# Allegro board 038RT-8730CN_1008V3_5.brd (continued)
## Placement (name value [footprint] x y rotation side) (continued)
NOREF#1801  -  []  182.03 253.76 90 top
NOREF#1802  -  []  328.29 191.82 0 top
NOREF#1803  -  []  242.32 277.38 0 top
NOREF#1804  -  []  227.55 359.7 0 top
NOREF#1805  -  []  388.3 185 90 top
NOREF#1806  -  []  428.82 224.67 0 top
NOREF#1807  -  []  232.52 183.21 90 top
NOREF#1808  -  []  508.3 275.9 90 top
NOREF#1809  -  []  333.23 206.23 0 top
NOREF#1810  -  []  410.97 245.28 0 top
NOREF#1811  -  []  324.25 177.55 0 top
NOREF#1812  -  []  406.87 194.07 0 top
NOREF#1813  -  []  407.38 198.01 0 top
NOREF#1814  -  []  364.8 184.64 0 top
NOREF#1815  -  []  311.08 208.98 0 top
NOREF#1816  -  []  389.18 198.29 90 top
NOREF#1817  -  []  410.3 206.6 90 top
NOREF#1818  -  []  320.97 84.76 0 top
NOREF#1819  -  []  333.28 209.37 90 top
NOREF#1820  -  []  333.32 257.97 0 top
NOREF#1821  -  []  196.58 203 90 top
NOREF#1822  -  []  279.69 296.22 0 top
NOREF#1823  -  []  406.9 260.19 0 top
NOREF#1824  -  []  297.43 210.27 90 top
NOREF#1825  -  []  520.17 246.5 90 top
NOREF#1826  -  []  502.07 202.24 90 top
NOREF#1827  -  []  404.75 228.96 90 top
NOREF#1828  -  []  275.93 207.58 90 top
NOREF#1829  -  []  429.34 243.1 0 top
NOREF#1830  -  []  281.8 294.95 0 top
NOREF#1831  -  []  320.37 202.42 0 top
NOREF#1832  -  []  323.07 86.06 0 top
NOREF#1833  -  []  403.93 127.85 90 top
NOREF#1834  -  []  393.3 230 0 top
NOREF#1835  -  []  325.7 184.32 90 top
NOREF#1836  -  []  373.23 262.51 0 top
NOREF#1837  -  []  269.18 260.49 90 top
NOREF#1838  -  []  296.84 171.61 0 top
NOREF#1839  -  []  408.95 196.35 0 top
NOREF#1840  -  []  204.8 424.5 90 top
NOREF#1841  -  []  521.42 202.06 0 top
NOREF#1842  -  []  477.82 173.08 0 top
NOREF#1843  -  []  294.58 298.52 90 top
NOREF#1844  -  []  413.23 206.23 0 top
NOREF#1845  -  []  305.3 188 90 top
NOREF#1846  -  []  209.66 201.6 90 top
NOREF#1847  -  []  452.91 239.5 0 top
NOREF#1848  -  []  412.33 204.49 0 top
NOREF#1849  -  []  375.13 272.93 90 top
NOREF#1850  -  []  182.03 282.65 90 top
NOREF#1851  -  []  306.68 169.03 0 top
NOREF#1852  -  []  354.08 200.75 90 top
NOREF#1853  -  []  269.18 258.29 90 top
NOREF#1854  -  []  362.9 209.33 0 top
NOREF#1855  -  []  187.33 183.21 0 top
NOREF#1856  -  []  284.75 288.95 90 top
NOREF#1857  -  []  146.75 421.44 0 top
NOREF#1858  -  []  477.74 261.14 0 top
NOREF#1859  -  []  290.99 252.65 0 top
NOREF#1860  -  []  367.56 210 0 top
NOREF#1861  -  []  328.5 270.01 0 top
NOREF#1862  -  []  336.14 200.99 0 top
NOREF#1863  -  []  230.64 271.58 0 top
NOREF#1864  -  []  364.53 264.54 90 top
NOREF#1865  -  []  329.7 176.75 0 top
NOREF#1866  -  []  329.66 195.8 90 top
NOREF#1867  -  []  482.51 99.06 0 top
NOREF#1868  -  []  548.8 23.5 90 top
NOREF#1869  -  []  52.77 6.56 0 top
NOREF#1870  -  []  335.42 199.88 90 top
NOREF#1871  -  []  238.16 228.9 90 top
NOREF#1872  -  []  247.68 245.33 0 top
NOREF#1873  -  []  254.87 194.3 90 top
NOREF#1874  -  []  454.88 278.39 0 top
NOREF#1875  -  []  409.3 191.52 90 top
NOREF#1876  -  []  366.25 195.33 0 top
NOREF#1877  -  []  239.54 299.08 0 top
NOREF#1878  -  []  284.8 188.34 0 top
NOREF#1879  -  []  268.3 225 0 top
NOREF#1880  -  []  363.34 213.34 0 top
NOREF#1881  -  []  327.65 84.79 90 top
NOREF#1882  -  []  443.36 102.82 0 top
NOREF#1883  -  []  428.36 281.49 0 top
NOREF#1884  -  []  403.63 206.35 0 top
NOREF#1885  -  []  442.87 257.56 0 top
NOREF#1886  -  []  376.84 171.61 0 top
NOREF#1887  -  []  497.31 212.21 90 top
NOREF#1888  -  []  409.87 196.73 0 top
NOREF#1889  -  []  374.43 263.38 90 top
NOREF#1890  -  []  370.67 250.47 90 top
NOREF#1891  -  []  253.73 219.45 0 top
NOREF#1892  -  []  349.34 243.1 0 top
NOREF#1893  -  []  386.14 179.9 90 top
NOREF#1894  -  []  410.07 245.6 0 top
NOREF#1895  -  []  450.32 102.82 0 top
NOREF#1896  -  []  233.84 210.26 90 top
NOREF#1897  -  []  511.9 279.95 90 top
NOREF#1898  -  []  227.67 287.48 0 top
NOREF#1899  -  []  288.3 205 0 top
NOREF#1900  -  []  333.29 151.39 0 top
NOREF#1901  -  []  408.3 205 90 top
NOREF#1902  -  []  308.3 245 90 top
NOREF#1903  -  []  272.8 23.5 90 top
NOREF#1904  -  []  328.53 227.49 0 top
NOREF#1905  -  []  321.7 269.33 0 top
NOREF#1906  -  []  219.44 253.19 90 top
NOREF#1907  -  []  179.95 227.88 90 top
NOREF#1908  -  []  216.24 271.58 0 top
NOREF#1909  -  []  208.01 295.88 90 top
NOREF#1910  -  []  493.99 285.39 0 top
NOREF#1911  -  []  368.54 251.43 0 top
NOREF#1912  -  []  514.57 195.59 90 top
NOREF#1913  -  []  520.17 255.14 90 top
NOREF#1914  -  []  428.82 265.97 0 top
NOREF#1915  -  []  329.7 209.37 90 top
NOREF#1916  -  []  249.33 239.72 0 top
NOREF#1917  -  []  52.77 405.06 0 top
NOREF#1918  -  []  328.89 191.43 0 top
NOREF#1919  -  []  453.25 245.41 90 top
NOREF#1920  -  []  505.42 294.03 0 top
NOREF#1921  -  []  321.57 201.78 90 top
NOREF#1922  -  []  453.76 170.92 0 top
NOREF#1923  -  []  410.97 192.03 90 top
NOREF#1924  -  []  326.35 187.8 0 top
NOREF#1925  -  []  285.3 262 0 top
NOREF#1926  -  []  414.11 86.06 0 top
NOREF#1927  -  []  400.89 251.48 90 top
NOREF#1928  -  []  288.3 265 0 top
NOREF#1929  -  []  186.51 258.1 0 top
NOREF#1930  -  []  477.74 192.56 0 top
NOREF#1931  -  []  227.67 184.61 0 top
NOREF#1932  -  []  259.35 302.27 0 top
NOREF#1933  -  []  288.24 300.71 90 top
NOREF#1934  -  []  391.54 183.1 0 top
NOREF#1935  -  []  407.82 269.36 90 top
NOREF#1936  -  []  284.53 263.69 90 top
NOREF#1937  -  []  413.32 260.2 0 top
NOREF#1938  -  []  31.09 337.83 90 top
NOREF#1939  -  []  325.98 187.8 0 top
NOREF#1940  -  []  219.44 271.58 90 top
NOREF#1941  -  []  265.98 263.69 0 top
NOREF#1942  -  []  403.33 264.33 0 top
NOREF#1943  -  []  213.05 131.66 0 top
NOREF#1944  -  []  272.38 290.7 90 top
NOREF#1945  -  []  414.5 189.29 90 top
NOREF#1946  -  []  323.43 93.57 90 top
NOREF#1947  -  []  409.93 179.45 0 top
NOREF#1948  -  []  508.3 207.32 90 top
NOREF#1949  -  []  343.63 396.4 0 top
NOREF#1950  -  []  459.82 218.67 90 top
NOREF#1951  -  []  373.32 257.97 0 top
NOREF#1952  -  []  191.18 271.58 0 top
NOREF#1953  -  []  193.38 278.84 0 top
NOREF#1954  -  []  430.14 189.48 0 top
NOREF#1955  -  []  323.34 273.34 0 top
NOREF#1956  -  []  400.37 260.97 0 top
NOREF#1957  -  []  349.3 283 0 top
NOREF#1958  -  []  328.82 209.11 90 top
NOREF#1959  -  []  284.1 259 0 top
NOREF#1960  -  []  155.68 253.76 0 top
NOREF#1961  -  []  367.08 197.69 0 top
NOREF#1962  -  []  50.8 465 0 top
NOREF#1963  -  []  182.03 236.93 0 top
NOREF#1964  -  []  326.51 167.49 90 top
NOREF#1965  -  []  401.57 262.44 90 top
NOREF#1966  -  []  182.03 202.64 90 top
NOREF#1967  -  []  13.59 370.31 90 top
NOREF#1968  -  []  413.47 192.26 0 top
NOREF#1969  -  []  366.33 255.34 90 top
NOREF#1970  -  []  208.01 253.19 90 top
NOREF#1971  -  []  217.72 377.26 90 top
NOREF#1972  -  []  269.3 223 0 top
NOREF#1973  -  []  181.48 224.7 90 top
NOREF#1974  -  []  369.3 251.52 90 top
NOREF#1975  -  []  193.33 292.92 0 top
NOREF#1976  -  []  373.02 196.8 0 top
NOREF#1977  -  []  454.88 286.79 0 top
NOREF#1978  -  []  372.19 252 90 top
NOREF#1979  -  []  211.84 261.59 0 top
NOREF#1980  -  []  293.34 191.84 0 top
NOREF#1981  -  []  412 84.76 0 top
NOREF#1982  -  []  514.57 191.19 90 top
NOREF#1983  -  []  508.74 296.69 90 top
NOREF#1984  -  []  408.3 205 0 top
NOREF#1985  -  []  128.63 387.18 0 top
NOREF#1986  -  []  175.18 199.36 0 top
NOREF#1987  -  []  458.33 169.65 90 top
NOREF#1988  -  []  310.61 379.8 0 top
NOREF#1989  -  []  505.67 245.66 90 top
NOREF#1990  -  []  288.51 196.36 0 top
NOREF#1991  -  []  331.52 194.76 90 top
NOREF#1992  -  []  459.65 361.76 90 top
NOREF#1993  -  []  395.48 194.44 90 top
NOREF#1994  -  []  286.08 200.19 0 top
NOREF#1995  -  []  374.73 175.45 0 top
NOREF#1996  -  []  459.82 259.97 90 top
NOREF#1997  -  []  439.67 178.77 90 top
NOREF#1998  -  []  272.28 201.89 0 top
NOREF#1999  -  []  488.59 232.71 0 top
NOREF#2000  -  []  30.51 353.75 90 top
NOREF#2001  -  []  406.55 171.34 90 top
NOREF#2002  -  []  368.89 251.43 0 top
NOREF#2003  -  []  494.38 382.36 0 top
NOREF#2004  -  []  256.93 274.01 90 top
NOREF#2005  -  []  369.82 186.49 0 top
NOREF#2006  -  []  329.67 209.11 90 top
NOREF#2007  -  []  221.62 183.21 0 top
NOREF#2008  -  []  433.17 322.65 90 top
NOREF#2009  -  []  442.87 195.99 0 top
NOREF#2010  -  []  317.13 95.22 90 top
NOREF#2011  -  []  517.92 250.53 0 top
NOREF#2012  -  []  233.84 271.58 90 top
NOREF#2013  -  []  366.29 238.5 90 top
NOREF#2014  -  []  405.7 196.69 0 top
NOREF#2015  -  []  286.9 200.19 0 top
NOREF#2016  -  []  189.51 190.05 90 top
NOREF#2017  -  []  393.33 201.92 0 top
NOREF#2018  -  []  453.25 211.76 0 top
NOREF#2019  -  []  260.08 161.59 90 top
NOREF#2020  -  []  386.14 239.9 90 top
NOREF#2021  -  []  414.57 280.31 90 top
NOREF#2022  -  []  363.33 266.03 0 top
NOREF#2023  -  []  466.06 360.96 90 top
NOREF#2024  -  []  230.64 237.29 0 top
NOREF#2025  -  []  46.32 412.09 90 top
NOREF#2026  -  []  323.33 206.03 0 top
NOREF#2027  -  []  326.9 260.19 0 top
NOREF#2028  -  []  196.58 175.97 90 top
NOREF#2029  -  []  327.65 82.22 90 top
NOREF#2030  -  []  291.52 194.76 90 top
NOREF#2031  -  []  300.3 273 0 top
NOREF#2032  -  []  342.54 75.65 0 top
NOREF#2033  -  []  389.3 283 0 top
NOREF#2034  -  []  291.55 189.53 90 top
NOREF#2035  -  []  285.7 246.14 90 top
NOREF#2036  -  []  257.93 230.02 0 top
NOREF#2037  -  []  373.3 257.5 90 top
NOREF#2038  -  []  383.61 136.74 0 top
NOREF#2039  -  []  465.73 282.2 90 top
NOREF#2040  -  []  365.3 202 0 top
NOREF#2041  -  []  285.68 245.52 90 top
NOREF#2042  -  []  406.57 194.43 90 top
NOREF#2043  -  []  285.98 187.8 0 top
NOREF#2044  -  []  491.79 276.99 0 top
NOREF#2045  -  []  511.37 267.36 0 top
NOREF#2046  -  []  202.61 278.84 0 top
NOREF#2047  -  []  454.88 183.92 0 top
NOREF#2048  -  []  330.8 293.85 0 top
NOREF#2049  -  []  285.7 196.05 0 top
NOREF#2050  -  []  400.8 260 0 top
NOREF#2051  -  []  313.3 240 90 top
NOREF#2052  -  []  453.76 205.21 0 top
NOREF#2053  -  []  471.77 359.7 0 top
NOREF#2054  -  []  417.78 228.89 90 top
NOREF#2055  -  []  505.92 291.03 0 top
NOREF#2056  -  []  514.57 264.17 90 top
NOREF#2057  -  []  366.38 296.27 90 top
NOREF#2058  -  []  308.3 185 90 top
NOREF#2059  -  []  211.05 377.23 0 top
NOREF#2060  -  []  366.3 254.08 90 top
NOREF#2061  -  []  500.02 290.83 90 top
NOREF#2062  -  []  457.37 375.96 0 top
NOREF#2063  -  []  242.32 243.09 0 top
NOREF#2064  -  []  329.61 259.55 90 top
NOREF#2065  -  []  333.02 196.8 0 top
NOREF#2066  -  []  414.58 288.89 0 top
NOREF#2067  -  []  373.03 213.89 0 top
NOREF#2068  -  []  382.62 166.16 90 top
NOREF#2069  -  []  164.15 -41.86 90 top
NOREF#2070  -  []  406.99 187.3 90 top
NOREF#2071  -  []  262.63 166.67 90 top
NOREF#2072  -  []  508.74 246.5 90 top
NOREF#2073  -  []  210.19 208.86 0 top
NOREF#2074  -  []  319.09 132.51 90 top
NOREF#2075  -  []  182.03 248.36 0 top
NOREF#2076  -  []  52.77 6.56 0 top
NOREF#2077  -  []  326.58 200.49 90 top
NOREF#2078  -  []  372.9 173.55 90 top
NOREF#2079  -  []  333.23 207.72 0 top
NOREF#2080  -  []  377.34 263.1 90 top
NOREF#2081  -  []  288.51 256.36 0 top
NOREF#2082  -  []  300.83 71.55 0 top
NOREF#2083  -  []  414.22 259.67 0 top
NOREF#2084  -  []  286.58 247.88 0 top
NOREF#2085  -  []  360.37 259.6 0 top
NOREF#2086  -  []  269.18 256.09 90 top
NOREF#2087  -  []  365.97 193.75 0 top
NOREF#2088  -  []  412.9 169.15 90 top
NOREF#2089  -  []  276.16 202.17 90 top
NOREF#2090  -  []  280.8 260 0 top
NOREF#2091  -  []  373.28 209.37 90 top
NOREF#2092  -  []  351.72 126.78 90 top
NOREF#2093  -  []  318.05 118.31 90 top
NOREF#2094  -  []  431.54 243.1 0 top
NOREF#2095  -  []  230.64 175.97 0 top
NOREF#2096  -  []  411.82 205.24 0 top
NOREF#2097  -  []  468.16 259.74 0 top
NOREF#2098  -  []  226.24 203 0 top
NOREF#2099  -  []  381.07 123.59 0 top
NOREF#2100  -  []  283.98 198.4 90 top
NOREF#2101  -  []  354.28 268.98 90 top
NOREF#2102  -  []  293.33 260.2 0 top
NOREF#2103  -  []  335.29 184.5 0 top
NOREF#2104  -  []  334.73 172.88 0 top
NOREF#2105  -  []  366.94 209.1 90 top
NOREF#2106  -  []  343.25 169.03 0 top
NOREF#2107  -  []  276.89 198.83 90 top
NOREF#2108  -  []  319.69 296.22 0 top
NOREF#2109  -  []  242.32 208.8 0 top
NOREF#2110  -  []  414.73 172.88 0 top
NOREF#2111  -  []  379.43 227.49 90 top
NOREF#2112  -  []  488.59 290.83 90 top
NOREF#2113  -  []  192.73 258.1 0 top
NOREF#2114  -  []  191.18 168.71 0 top
NOREF#2115  -  []  179.95 250.74 90 top
NOREF#2116  -  []  366.33 247.99 90 top
NOREF#2117  -  []  336.44 260.67 0 top
NOREF#2118  -  []  406.4 287.55 90 top
NOREF#2119  -  []  468.16 225.45 0 top
NOREF#2120  -  []  477.74 268.4 0 top
NOREF#2121  -  []  284.8 196.37 0 top
NOREF#2122  -  []  276.79 294.51 0 top
NOREF#2123  -  []  337.34 263.1 90 top
NOREF#2124  -  []  208.01 203 90 top
NOREF#2125  -  []  219.44 237.29 90 top
NOREF#2126  -  []  285.68 255.34 90 top
NOREF#2127  -  []  361.57 199.65 90 top
NOREF#2128  -  []  228.44 210.26 0 top
NOREF#2129  -  []  400.37 200.29 0 top
NOREF#2130  -  []  484.5 170.54 90 top
NOREF#2131  -  []  309.3 223 0 top
NOREF#2132  -  []  285.7 267.17 0 top
NOREF#2133  -  []  412.33 265.91 0 top
NOREF#2134  -  []  292.33 267.4 0 top
NOREF#2135  -  []  374.67 191.62 90 top
NOREF#2136  -  []  459.82 252.96 90 top
NOREF#2137  -  []  280.37 259.6 0 top
NOREF#2138  -  []  477.16 273.79 90 top
NOREF#2139  -  []  498.22 360.96 90 top
NOREF#2140  -  []  259.78 233.58 0 top
NOREF#2141  -  []  271.3 222 0 top
NOREF#2142  -  []  182.03 225.5 0 top
NOREF#2143  -  []  233.84 237.29 90 top
NOREF#2144  -  []  229.02 85.95 0 top
NOREF#2145  -  []  369.67 209.11 90 top
NOREF#2146  -  []  295.29 244.5 0 top
NOREF#2147  -  []  301.44 169.36 0 top
NOREF#2148  -  []  210.19 286.08 0 top
NOREF#2149  -  []  286.3 193.44 90 top
NOREF#2150  -  []  240.95 258.24 0 top
NOREF#2151  -  []  317.15 228.96 0 top
NOREF#2152  -  []  369.77 252.68 0 top
NOREF#2153  -  []  329.29 195.34 90 top
NOREF#2154  -  []  196.33 223.81 90 top
NOREF#2155  -  []  446.07 165.85 90 top
NOREF#2156  -  []  283.66 273.64 90 top
NOREF#2157  -  []  221.09 201.6 90 top
NOREF#2158  -  []  366.96 142.02 90 top
NOREF#2159  -  []  477.16 208.41 0 top
NOREF#2160  -  []  290.67 251.75 90 top
NOREF#2161  -  []  437.91 103.62 0 top
NOREF#2162  -  []  521.42 190.63 0 top
NOREF#2163  -  []  365.68 195.34 90 top
NOREF#2164  -  []  485.88 169.52 90 top
NOREF#2165  -  []  179.95 170.73 90 top
NOREF#2166  -  []  284.8 186.46 0 top
NOREF#2167  -  []  454.88 218.21 0 top
NOREF#2168  -  []  282.9 209.32 0 top
NOREF#2169  -  []  405.92 226.51 0 top
NOREF#2170  -  []  417.34 204.47 90 top
NOREF#2171  -  []  502.07 167.95 90 top
NOREF#2172  -  []  369.11 251.32 90 top
NOREF#2173  -  []  500.02 232.71 0 top
NOREF#2174  -  []  429.36 166.16 90 top
NOREF#2175  -  []  52.77 6.56 0 top
NOREF#2176  -  []  329.13 251.83 90 top
NOREF#2177  -  []  325.68 255.34 90 top
NOREF#2178  -  []  309.3 283 0 top
NOREF#2179  -  []  508.74 212.21 90 top
NOREF#2180  -  []  405.98 187.8 0 top
NOREF#2181  -  []  337.34 264.47 90 top
NOREF#2182  -  []  321.8 294.95 0 top
NOREF#2183  -  []  323.63 264.65 0 top
NOREF#2184  -  []  414.57 222.51 90 top
NOREF#2185  -  []  404.8 186.46 90 top
NOREF#2186  -  []  453.02 216.31 90 top
NOREF#2187  -  []  333.28 269.37 90 top
NOREF#2188  -  []  366.86 77.94 0 top
NOREF#2189  -  []  405.7 186.14 90 top
NOREF#2190  -  []  191.18 203 0 top
NOREF#2191  -  []  407.56 270 0 top
NOREF#2192  -  []  349.3 186 90 top
NOREF#2193  -  []  368.09 255.99 0 top
NOREF#2194  -  []  237.43 231.77 0 top
NOREF#2195  -  []  297.34 260.35 90 top
NOREF#2196  -  []  244.11 194.94 90 top
NOREF#2197  -  []  294.57 218.11 90 top
NOREF#2198  -  []  372.7 250.29 0 top
NOREF#2199  -  []  377.34 264.47 90 top
NOREF#2200  -  []  362.9 269.33 0 top
NOREF#2201  -  []  296.44 204.79 0 top
NOREF#2202  -  []  336.84 171.61 0 top
NOREF#2203  -  []  351.54 183.1 0 top
NOREF#2204  -  []  326.57 194.43 90 top
NOREF#2205  -  []  294.3 260.8 90 top
NOREF#2206  -  []  395.24 294.13 0 top
NOREF#2207  -  []  414.12 300.11 0 top
NOREF#2208  -  []  267.91 225.75 90 top
NOREF#2209  -  []  553.44 322.27 90 top
NOREF#2210  -  []  50.8 465 0 top
NOREF#2211  -  []  413.93 213.57 0 top
NOREF#2212  -  []  452.5 88.62 0 top
NOREF#2213  -  []  334.33 147.75 90 top
NOREF#2214  -  []  395.1 202.13 90 top
NOREF#2215  -  []  373.32 259.35 0 top
NOREF#2216  -  []  233.84 278.84 90 top
NOREF#2217  -  []  504.28 383.9 90 top
NOREF#2218  -  []  403.66 213.64 90 top
NOREF#2219  -  []  291.05 276.46 90 top
NOREF#2220  -  []  374.58 288.89 0 top
NOREF#2221  -  []  360.37 209.76 0 top
NOREF#2222  -  []  480.36 285.39 0 top
NOREF#2223  -  []  505.67 177.08 90 top
NOREF#2224  -  []  330.67 250.47 90 top
NOREF#2225  -  []  340.3 257 90 top
NOREF#2226  -  []  491.79 232.71 0 top
NOREF#2227  -  []  489.17 226.85 0 top
NOREF#2228  -  []  405.7 207.17 0 top
NOREF#2229  -  []  477.16 267 0 top
NOREF#2230  -  []  413.22 207.72 0 top
NOREF#2231  -  []  413.36 250.09 0 top
NOREF#2232  -  []  406.3 253.44 90 top
NOREF#2233  -  []  377.78 288.89 90 top
NOREF#2234  -  []  455.27 379.8 0 top
NOREF#2235  -  []  273.3 230 0 top
NOREF#2236  -  []  271.3 282 0 top
NOREF#2237  -  []  269.24 227.48 90 top
NOREF#2238  -  []  251.53 246.73 0 top
NOREF#2239  -  []  368.89 191.89 0 top
NOREF#2240  -  []  247.68 204.03 0 top
NOREF#2241  -  []  327.88 209.1 90 top
NOREF#2242  -  []  211.13 97.97 0 top
NOREF#2243  -  []  294.66 72.52 0 top
NOREF#2244  -  []  363.37 196.69 0 top
NOREF#2245  -  []  182.03 225.5 90 top
NOREF#2246  -  []  401.57 198.96 90 top
NOREF#2247  -  []  219.44 261.59 90 top
NOREF#2248  -  []  363.01 153.19 0 top
NOREF#2249  -  []  284.2 254.4 0 top
NOREF#2250  -  []  404.2 254.4 0 top
NOREF#2251  -  []  284.8 256.37 0 top
NOREF#2252  -  []  222.39 361.76 0 top
NOREF#2253  -  []  332.53 116.51 90 top
NOREF#2254  -  []  403.63 264.65 0 top
NOREF#2255  -  []  269.3 223 0 top
NOREF#2256  -  []  453.25 246.05 0 top
NOREF#2257  -  []  314.08 200.75 90 top
NOREF#2258  -  []  446.4 187.57 90 top
NOREF#2259  -  []  286.9 247.37 90 top
NOREF#2260  -  []  280.37 199.6 0 top
NOREF#2261  -  []  329.31 251.29 90 top
NOREF#2262  -  []  285.24 74.78 0 top
NOREF#2263  -  []  321.04 121.95 0 top
NOREF#2264  -  []  50.8 5 0 top
NOREF#2265  -  []  405.3 202 0 top
NOREF#2266  -  []  328.08 195.55 0 top
NOREF#2267  -  []  204.81 218.9 0 top
NOREF#2268  -  []  284.8 246.46 90 top
NOREF#2269  -  []  367.93 184.02 90 top
NOREF#2270  -  []  219.44 175.97 90 top
NOREF#2271  -  []  418.68 84.79 90 top
NOREF#2272  -  []  268.11 285.26 0 top
NOREF#2273  -  []  433.52 226.72 90 top
NOREF#2274  -  []  511.37 278.79 0 top
NOREF#2275  -  []  198.76 243.15 0 top
NOREF#2276  -  []  376.14 260.99 0 top
NOREF#2277  -  []  337.78 228.89 90 top
NOREF#2278  -  []  175.18 267.94 0 top
NOREF#2279  -  []  407.59 256.03 0 top
NOREF#2280  -  []  416.8 199 90 top
NOREF#2281  -  []  501.06 377.26 90 top
NOREF#2282  -  []  211.84 253.19 0 top
NOREF#2283  -  []  425.45 295.32 0 top
NOREF#2284  -  []  319.47 203.4 0 top
NOREF#2285  -  []  520.87 280.98 90 top
NOREF#2286  -  []  407.28 199.55 90 top
NOREF#2287  -  []  391.56 177.54 0 top
NOREF#2288  -  []  405.7 248.01 0 top
NOREF#2289  -  []  351.12 88.56 90 top
NOREF#2290  -  []  513.7 188.5 90 top
NOREF#2291  -  []  193.38 184.61 0 top
NOREF#2292  -  []  376.14 265.11 0 top
NOREF#2293  -  []  479.93 171.81 0 top
NOREF#2294  -  []  296.8 199 90 top
NOREF#2295  -  []  489.17 252.5 0 top
NOREF#2296  -  []  349.57 121.95 0 top
NOREF#2297  -  []  280.37 209.76 0 top
NOREF#2298  -  []  321.04 152.43 0 top
NOREF#2299  -  []  287.38 258.01 0 top
NOREF#2300  -  []  329.67 269.11 90 top
NOREF#2301  -  []  287 187.55 90 top
NOREF#2302  -  []  315.5 287.55 0 top
NOREF#2303  -  []  50.8 5 0 top
NOREF#2304  -  []  282.9 354.77 0 top
NOREF#2305  -  []  333.59 106.22 90 top
NOREF#2306  -  []  451.12 284.49 0 top
NOREF#2307  -  []  406.58 187.88 0 top
NOREF#2308  -  []  351.3 282 0 top
NOREF#2309  -  []  367.36 200.49 90 top
NOREF#2310  -  []  402.3 196.5 0 top
NOREF#2311  -  []  477.16 290.83 90 top
NOREF#2312  -  []  328.08 255.55 0 top
NOREF#2313  -  []  194.2 133.35 0 top
NOREF#2314  -  []  337.48 67.46 90 top
NOREF#2315  -  []  453.52 95.22 90 top
NOREF#2316  -  []  461.95 379.82 90 top
NOREF#2317  -  []  237.33 373.84 0 top
NOREF#2318  -  []  333.34 191.84 0 top
NOREF#2319  -  []  194.53 260.15 90 top
NOREF#2320  -  []  305.98 203.69 0 top
NOREF#2321  -  []  324.1 259 90 top
NOREF#2322  -  []  293.03 197.65 0 top
NOREF#2323  -  []  310.18 77.65 0 top
NOREF#2324  -  []  334.3 268.85 90 top
NOREF#2325  -  []  290.9 202.85 90 top
NOREF#2326  -  []  193.38 271.58 0 top
NOREF#2327  -  []  366.33 187.99 90 top
NOREF#2328  -  []  280.35 208.16 90 top
NOREF#2329  -  []  296.24 199.17 0 top
NOREF#2330  -  []  186.38 109.62 90 top
NOREF#2331  -  []  439.67 192.79 90 top
NOREF#2332  -  []  52.77 6.56 0 top
NOREF#2333  -  []  355.6 252.3 90 top
NOREF#2334  -  []  294.22 259.67 0 top
NOREF#2335  -  []  223.27 218.9 0 top
NOREF#2336  -  []  281.57 201.78 90 top
NOREF#2337  -  []  300.87 216.46 90 top
NOREF#2338  -  []  360.3 237 90 top
NOREF#2339  -  []  280.3 233 0 top
NOREF#2340  -  []  360.37 203.08 0 top
NOREF#2341  -  []  454.13 279.44 90 top
NOREF#2342  -  []  299.43 287.49 90 top
NOREF#2343  -  []  404.8 186.46 0 top
NOREF#2344  -  []  510.1 222.79 0 top
NOREF#2345  -  []  509.5 177.08 0 top
NOREF#2346  -  []  340.3 213 0 top
NOREF#2347  -  []  198.76 201.6 0 top
NOREF#2348  -  []  294.43 205.59 90 top
NOREF#2349  -  []  410.07 190.47 0 top
NOREF#2350  -  []  332.33 265.91 0 top
NOREF#2351  -  []  328.3 205 0 top
NOREF#2352  -  []  395.6 252.3 90 top
NOREF#2353  -  []  452.5 86.06 0 top
NOREF#2354  -  []  363.83 69.49 0 top
NOREF#2355  -  []  416.8 259 90 top
NOREF#2356  -  []  508.74 289.43 90 top
NOREF#2357  -  []  333.93 273.57 0 top
NOREF#2358  -  []  435.67 280.01 90 top
NOREF#2359  -  []  455.27 382.36 0 top
NOREF#2360  -  []  22.4 339.42 90 top
NOREF#2361  -  []  317.29 153.19 0 top
NOREF#2362  -  []  300.83 74.6 0 top
NOREF#2363  -  []  211.84 203 0 top
NOREF#2364  -  []  318.05 136.15 0 top
NOREF#2365  -  []  193.38 203 0 top
NOREF#2366  -  []  294.43 203.38 90 top
NOREF#2367  -  []  302.94 70.28 0 top
NOREF#2368  -  []  303.3 250 90 top
NOREF#2369  -  []  360.89 191.48 90 top
NOREF#2370  -  []  333.32 200.2 0 top
NOREF#2371  -  []  329.34 246.99 0 top
NOREF#2372  -  []  290.76 195.38 0 top
NOREF#2373  -  []  198.76 167.31 0 top
NOREF#2374  -  []  520.87 269.55 90 top
NOREF#2375  -  []  293.23 262.51 0 top
NOREF#2376  -  []  233.84 175.97 90 top
NOREF#2377  -  []  354.08 260.75 90 top
NOREF#2378  -  []  258.58 252.34 90 top
NOREF#2379  -  []  288.29 191.82 0 top
NOREF#2380  -  []  216.24 168.71 0 top
NOREF#2381  -  []  336.24 199.17 0 top
NOREF#2382  -  []  412.38 228.89 0 top
NOREF#2383  -  []  412.33 263.7 0 top
NOREF#2384  -  []  288.82 209.11 90 top
NOREF#2385  -  []  315 361.76 90 top
NOREF#2386  -  []  368.51 256.36 0 top
NOREF#2387  -  []  366.58 187.88 0 top
NOREF#2388  -  []  280.46 87.33 0 top
NOREF#2389  -  []  306.68 208.98 0 top
NOREF#2390  -  []  451.91 234.11 0 top
NOREF#2391  -  []  319.47 262.74 0 top
NOREF#2392  -  []  290.18 288.89 0 top
NOREF#2393  -  []  363.01 131.75 90 top
NOREF#2394  -  []  223.27 253.19 0 top
NOREF#2395  -  []  292.33 203.7 0 top
NOREF#2396  -  []  326.55 173.54 90 top
NOREF#2397  -  []  334.57 280.31 90 top
NOREF#2398  -  []  326.9 247.37 90 top
NOREF#2399  -  []  376.44 264.79 0 top
NOREF#2400  -  []  269.3 246 90 top
NOREF#2401  -  []  311.3 248 90 top
NOREF#2402  -  []  196.58 253.19 90 top
NOREF#2403  -  []  334.22 199.67 0 top
NOREF#2404  -  []  406.9 255.41 90 top
NOREF#2405  -  []  300.87 276.46 90 top
NOREF#2406  -  []  280.46 84.76 0 top
NOREF#2407  -  []  406.87 254.07 0 top
NOREF#2408  -  []  217.72 379.82 90 top
NOREF#2409  -  []  330.32 195.4 0 top
NOREF#2410  -  []  360.35 208.16 90 top
NOREF#2411  -  []  327.65 82.22 90 top
NOREF#2412  -  []  489.17 199.82 0 top
NOREF#2413  -  []  477.16 222.25 90 top
NOREF#2414  -  []  52.77 68.06 0 top
NOREF#2415  -  []  286.3 207 0 top
NOREF#2416  -  []  386.14 173.54 90 top
NOREF#2417  -  []  285.68 195.34 90 top
NOREF#2418  -  []  311.54 243.1 0 top
NOREF#2419  -  []  204.81 168.71 0 top
NOREF#2420  -  []  223.27 193.01 0 top
NOREF#2421  -  []  361.81 297.54 0 top
NOREF#2422  -  []  546.8 446.5 0 top
NOREF#2423  -  []  230.64 244.55 0 top
NOREF#2424  -  []  328.53 287.49 0 top
NOREF#2425  -  []  328.89 251.89 0 top
NOREF#2426  -  []  235.93 80.76 90 top
NOREF#2427  -  []  286.57 255.72 0 top
NOREF#2428  -  []  320.97 84.76 0 top
NOREF#2429  -  []  416.24 259.17 0 top
NOREF#2430  -  []  386.68 268.98 0 top
NOREF#2431  -  []  269.3 186 90 top
NOREF#2432  -  []  288.66 251.82 0 top
NOREF#2433  -  []  407.08 197.69 0 top
NOREF#2434  -  []  465.73 213.62 90 top
NOREF#2435  -  []  155.68 185.18 0 top
NOREF#2436  -  []  497.91 136.49 0 top
NOREF#2437  -  []  376.44 203.42 0 top
NOREF#2438  -  []  210.19 167.31 0 top
NOREF#2439  -  []  417.34 260.35 90 top
NOREF#2440  -  []  465.73 179.33 90 top
NOREF#2441  -  []  369.82 246.49 0 top
NOREF#2442  -  []  362.3 256.5 0 top
NOREF#2443  -  []  204.81 271.58 0 top
NOREF#2444  -  []  503.87 154.21 0 top
NOREF#2445  -  []  365.7 196.69 0 top
NOREF#2446  -  []  327.36 260.49 90 top
NOREF#2447  -  []  409.13 251.83 90 top
NOREF#2448  -  []  294.5 249.29 90 top
NOREF#2449  -  []  286.3 253.44 90 top
NOREF#2450  -  []  325.3 262 0 top
NOREF#2451  -  []  202.61 237.29 0 top
NOREF#2452  -  []  503.22 259.74 0 top
NOREF#2453  -  []  221.09 235.89 90 top
NOREF#2454  -  []  364.8 268.5 0 top
NOREF#2455  -  []  283.63 206.35 0 top
NOREF#2456  -  []  280.8 200 0 top
NOREF#2457  -  []  348.53 120.26 90 top
NOREF#2458  -  []  407 247.28 90 top
NOREF#2459  -  []  351.3 248 90 top
NOREF#2460  -  []  451.12 250.2 0 top
NOREF#2461  -  []  52.77 405.06 0 top
NOREF#2462  -  []  364.81 137.19 0 top
NOREF#2463  -  []  401.55 225.71 0 top
NOREF#2464  -  []  459.82 177.37 90 top
NOREF#2465  -  []  459.65 361.76 0 top
NOREF#2466  -  []  410.07 250.47 0 top
NOREF#2467  -  []  319.47 270.08 0 top
NOREF#2468  -  []  417.27 177.85 0 top
NOREF#2469  -  []  364.75 220.31 90 top
NOREF#2470  -  []  517.92 261.96 0 top
NOREF#2471  -  []  325.7 248.01 0 top
NOREF#2472  -  []  288.89 191.43 0 top
NOREF#2473  -  []  333.29 133.55 90 top
NOREF#2474  -  []  324.8 187.74 90 top
NOREF#2475  -  []  314.08 200.75 0 top
NOREF#2476  -  []  368.95 196.35 0 top
NOREF#2477  -  []  253.02 172.11 0 top
NOREF#2478  -  []  289.7 209.37 90 top
NOREF#2479  -  []  383.3 280 0 top
NOREF#2480  -  []  360.37 260.29 0 top
NOREF#2481  -  []  321.04 137.19 0 top
NOREF#2482  -  []  286.94 269.1 90 top
NOREF#2483  -  []  377.34 203.1 90 top
NOREF#2484  -  []  346.14 183.1 0 top
NOREF#2485  -  []  175.18 176.5 0 top
NOREF#2486  -  []  282.56 86.06 0 top
NOREF#2487  -  []  334.57 218.11 90 top
NOREF#2488  -  []  273.04 73.43 90 top
NOREF#2489  -  []  232.52 260.19 90 top
NOREF#2490  -  []  370.18 228.89 0 top
NOREF#2491  -  []  404.8 246.46 90 top
NOREF#2492  -  []  325.13 188.64 0 top
NOREF#2493  -  []  227.67 227.3 0 top
NOREF#2494  -  []  409.42 194.63 0 top
NOREF#2495  -  []  293.03 257.65 0 top
NOREF#2496  -  []  366.4 227.56 90 top
NOREF#2497  -  []  394.08 200.75 90 top
NOREF#2498  -  []  329.3 191.52 90 top
NOREF#2499  -  []  481.55 373.84 0 top
NOREF#2500  -  []  286.58 260.49 90 top
NOREF#2501  -  []  348.53 135.5 90 top
NOREF#2502  -  []  370.3 263 90 top
NOREF#2503  -  []  390.87 296.74 90 top
NOREF#2504  -  []  404.8 256.37 0 top
NOREF#2505  -  []  374.73 170.29 0 top
NOREF#2506  -  []  257.3 228.95 0 top
NOREF#2507  -  []  328.88 259.55 90 top
NOREF#2508  -  []  287.38 198.01 0 top
NOREF#2509  -  []  368.29 191.82 0 top
NOREF#2510  -  []  209.66 208.86 90 top
NOREF#2511  -  []  367.59 256.03 0 top
NOREF#2512  -  []  329.35 210.01 0 top
NOREF#2513  -  []  210.19 277.44 0 top
NOREF#2514  -  []  289.3 251.52 90 top
NOREF#2515  -  []  292.41 209.11 90 top
NOREF#2516  -  []  289.35 210.01 0 top
NOREF#2517  -  []  418.68 82.22 90 top
NOREF#2518  -  []  306.67 304.88 0 top
NOREF#2519  -  []  203.98 360.96 0 top
NOREF#2520  -  []  181.48 178.98 90 top
NOREF#2521  -  []  401.21 252.38 0 top
NOREF#2522  -  []  514.49 359.7 90 top
NOREF#2523  -  []  520.17 177.92 90 top
NOREF#2524  -  []  295.29 178.14 0 top
NOREF#2525  -  []  293.23 204.02 0 top
NOREF#2526  -  []  187.33 251.79 0 top
NOREF#2527  -  []  373.28 269.37 90 top
NOREF#2528  -  []  219.44 203 90 top
NOREF#2529  -  []  410.55 269.37 90 top
NOREF#2530  -  []  401.55 285.71 0 top
NOREF#2531  -  []  332.17 189.51 90 top
NOREF#2532  -  []  465.73 273.79 90 top
NOREF#2533  -  []  385.03 267.58 0 top
NOREF#2534  -  []  500.02 256.54 90 top
NOREF#2535  -  []  446.29 238.5 90 top
NOREF#2536  -  []  429.08 90.74 0 top
NOREF#2537  -  []  313.3 180 90 top
NOREF#2538  -  []  359.15 268.8 0 top
NOREF#2539  -  []  477.74 218.21 0 top
NOREF#2540  -  []  404.75 218.11 90 top
NOREF#2541  -  []  268.3 185 90 top
NOREF#2542  -  []  306.68 268.98 0 top
NOREF#2543  -  []  404.57 196.05 90 top
NOREF#2544  -  []  516.65 213.88 0 top
NOREF#2545  -  []  317.29 146.99 90 top
NOREF#2546  -  []  514.57 179.76 90 top
NOREF#2547  -  []  412.01 296.22 0 top
NOREF#2548  -  []  365.1 254.08 0 top
NOREF#2549  -  []  289.42 254.63 0 top
NOREF#2550  -  []  232.52 225.9 90 top
NOREF#2551  -  []  488.59 256.54 90 top
NOREF#2552  -  []  200.41 168.71 0 top
NOREF#2553  -  []  331.82 205.24 0 top
NOREF#2554  -  []  488.59 216.81 0 top
NOREF#2555  -  []  292.17 249.51 90 top
NOREF#2556  -  []  334.43 267.08 90 top
NOREF#2557  -  []  361.57 259.65 90 top
NOREF#2558  -  []  505.73 364.96 90 top
NOREF#2559  -  []  50.8 5 0 top
NOREF#2560  -  []  450.39 89.89 0 top
NOREF#2561  -  []  226.93 275.78 90 top
NOREF#2562  -  []  287 247.28 90 top
NOREF#2563  -  []  325.76 200.49 90 top
NOREF#2564  -  []  326.99 247.3 90 top
NOREF#2565  -  []  326.9 196.05 90 top
NOREF#2566  -  []  276.89 198.83 90 top
NOREF#2567  -  []  198.76 260.19 0 top
NOREF#2568  -  []  407.68 200.19 0 top
NOREF#2569  -  []  408.09 260.49 90 top
NOREF#2570  -  []  306.14 239.9 90 top
NOREF#2571  -  []  420.87 276.46 90 top
NOREF#2572  -  []  290.3 206.6 90 top
NOREF#2573  -  []  363.77 136.15 0 top
NOREF#2574  -  []  290.07 192.35 0 top
NOREF#2575  -  []  404.48 195.99 0 top
NOREF#2576  -  []  351.08 268.98 0 top
NOREF#2577  -  []  324.8 245.52 0 top
NOREF#2578  -  []  330.3 263 90 top
NOREF#2579  -  []  284.5 246.78 0 top
NOREF#2580  -  []  361.7 269.33 0 top
NOREF#2581  -  []  514.57 239.1 90 top
NOREF#2582  -  []  296.51 66.77 90 top
NOREF#2583  -  []  433.26 335.54 0 top
NOREF#2584  -  []  254.87 262.88 90 top
NOREF#2585  -  []  376.44 263.42 0 top
NOREF#2586  -  []  284.1 199 0 top
NOREF#2587  -  []  414.22 199.67 0 top
NOREF#2588  -  []  366.33 195.34 90 top
NOREF#2589  -  []  374.57 280.31 90 top
NOREF#2590  -  []  296.84 171.61 0 top
NOREF#2591  -  []  407 187.28 90 top
NOREF#2592  -  []  337.34 200.35 90 top
NOREF#2593  -  []  393.33 261.92 0 top
NOREF#2594  -  []  292.68 350.14 90 top
NOREF#2595  -  []  454.88 252.5 0 top
NOREF#2596  -  []  468.16 301.29 0 top
NOREF#2597  -  []  336.14 263.74 0 top
NOREF#2598  -  []  251.53 274.01 0 top
NOREF#2599  -  []  286.57 195.72 0 top
NOREF#2600  -  []  364.8 186.46 90 top
NOREF#2601  -  []  406.98 302.94 0 top
NOREF#2602  -  []  357.15 288.95 0 top
NOREF#2603  -  []  289.77 252.68 0 top
NOREF#2604  -  []  50.8 465 0 top
NOREF#2605  -  []  230.64 168.71 0 top
NOREF#2606  -  []  55.8 0 90 top
NOREF#2607  -  []  477.16 301.29 0 top
NOREF#2608  -  []  284.8 185.52 0 top
NOREF#2609  -  []  327 187.55 90 top
NOREF#2610  -  []  175.18 222.22 0 top
NOREF#2611  -  []  219.44 210.26 90 top
NOREF#2612  -  []  322.3 196.5 0 top
NOREF#2613  -  []  291.07 196.08 90 top
NOREF#2614  -  []  324.8 246.46 90 top
NOREF#2615  -  []  372.33 267.4 0 top
NOREF#2616  -  []  400.37 209.76 0 top
NOREF#2617  -  []  260.3 213 0 top
NOREF#2618  -  []  334.73 172.88 0 top
NOREF#2619  -  []  221.62 294.48 0 top
NOREF#2620  -  []  299.4 293.92 0 top
NOREF#2621  -  []  477.74 226.85 0 top
NOREF#2622  -  []  326.58 260.49 90 top
NOREF#2623  -  []  367.36 260.49 90 top
NOREF#2624  -  []  406.9 187.37 90 top
NOREF#2625  -  []  366.58 247.88 0 top
NOREF#2626  -  []  380.3 273 0 top
NOREF#2627  -  []  521.42 213.49 0 top
NOREF#2628  -  []  508.74 255.14 90 top
NOREF#2629  -  []  409.77 192.68 0 top
NOREF#2630  -  []  287.45 194.68 90 top
NOREF#2631  -  []  286.9 267.17 0 top
NOREF#2632  -  []  400.21 169.14 90 top
NOREF#2633  -  []  420.81 206.84 90 top
NOREF#2634  -  []  375.29 244.5 0 top
NOREF#2635  -  []  365.7 267.17 0 top
NOREF#2636  -  []  428.82 258.96 0 top
NOREF#2637  -  []  330.3 266.6 90 top
NOREF#2638  -  []  406.82 247.81 90 top
NOREF#2639  -  []  446.29 178.5 90 top
NOREF#2640  -  []  358.83 267.9 90 top
NOREF#2641  -  []  408.09 199.55 90 top
NOREF#2642  -  []  340.3 197 90 top
NOREF#2643  -  []  274.47 82 90 top
NOREF#2644  -  []  263.29 225.75 90 top
NOREF#2645  -  []  326.29 178.5 90 top
NOREF#2646  -  []  370.55 269.37 90 top
NOREF#2647  -  []  251.53 205.43 0 top
NOREF#2648  -  []  204.81 287.48 0 top
NOREF#2649  -  []  221.62 191.61 0 top
NOREF#2650  -  []  508.3 236.53 90 top
NOREF#2651  -  []  359.7 296.22 0 top
NOREF#2652  -  []  366.9 195.41 90 top
NOREF#2653  -  []  324.53 205.39 90 top
NOREF#2654  -  []  376.24 199.17 0 top
NOREF#2655  -  []  514.57 271.2 90 top
NOREF#2656  -  []  406.58 247.42 0 top
NOREF#2657  -  []  324.8 186.46 0 top
NOREF#2658  -  []  368.08 255.55 0 top
NOREF#2659  -  []  517.92 193.38 0 top
NOREF#2660  -  []  286.9 255.41 90 top
NOREF#2661  -  []  284.75 282.51 90 top
NOREF#2662  -  []  389.18 200.49 90 top
NOREF#2663  -  []  508.74 280.79 90 top
NOREF#2664  -  []  327 247.55 90 top
NOREF#2665  -  []  406.25 255.33 0 top
NOREF#2666  -  []  398.83 267.9 90 top
NOREF#2667  -  []  374.58 295.32 0 top
NOREF#2668  -  []  360.37 202.42 0 top
NOREF#2669  -  []  330.55 209.37 90 top
NOREF#2670  -  []  273.3 290 0 top
NOREF#2671  -  []  249.33 288.03 0 top
NOREF#2672  -  []  242.47 224.25 90 top
NOREF#2673  -  []  500.02 294.03 0 top
NOREF#2674  -  []  514.57 248.34 90 top
NOREF#2675  -  []  286.58 187.88 0 top
NOREF#2676  -  []  -7.33 348.27 90 top
NOREF#2677  -  []  208.01 271.58 90 top
NOREF#2678  -  []  323.37 256.69 0 top
NOREF#2679  -  []  200.41 184.61 0 top
NOREF#2680  -  []  281.57 258.96 90 top
NOREF#2681  -  []  477.31 98.31 90 top
NOREF#2682  -  []  408.66 251.82 0 top
NOREF#2683  -  []  343.3 280 0 top
NOREF#2684  -  []  230.87 218.9 90 top
NOREF#2685  -  []  403.98 198.4 90 top
NOREF#2686  -  []  374.67 251.62 90 top
NOREF#2687  -  []  408.41 200.19 0 top
NOREF#2688  -  []  405.1 194.72 0 top
NOREF#2689  -  []  520.67 373.84 0 top
NOREF#2690  -  []  521.42 219.42 90 top
NOREF#2691  -  []  223.27 261.59 0 top
NOREF#2692  -  []  290.99 192.65 0 top
NOREF#2693  -  []  408.29 191.82 0 top
NOREF#2694  -  []  286.57 254.43 90 top
NOREF#2695  -  []  366.99 247.5 90 top
NOREF#2696  -  []  264.23 166.21 90 top
NOREF#2697  -  []  371.8 261.5 90 top
NOREF#2698  -  []  359.47 200.61 0 top
NOREF#2699  -  []  365.76 260.49 90 top
NOREF#2700  -  []  198.76 235.89 0 top
NOREF#2701  -  []  363.01 137.95 0 top
NOREF#2702  -  []  293.23 264.81 0 top
NOREF#2703  -  []  193.33 190.05 0 top
NOREF#2704  -  []  13.59 365.99 0 top
NOREF#2705  -  []  410.18 288.89 0 top
NOREF#2706  -  []  413.23 264.02 0 top
NOREF#2707  -  []  225.47 287.48 0 top
NOREF#2708  -  []  323.07 86.06 0 top
NOREF#2709  -  []  209.66 277.44 90 top
NOREF#2710  -  []  346.12 99.06 0 top
NOREF#2711  -  []  317.29 379.82 90 top
NOREF#2712  -  []  520.17 193.82 90 top
NOREF#2713  -  []  345.03 207.58 0 top
NOREF#2714  -  []  310.61 382.36 0 top
NOREF#2715  -  []  327.56 270 0 top
NOREF#2716  -  []  455.27 382.36 0 top
NOREF#2717  -  []  301.41 170.34 90 top
NOREF#2718  -  []  457.07 84.79 90 top
NOREF#2719  -  []  187.33 208.86 0 top
NOREF#2720  -  []  209.66 191.61 90 top
NOREF#2721  -  []  294.57 280.31 90 top
NOREF#2722  -  []  302.64 75.7 90 top
NOREF#2723  -  []  182.03 251.55 90 top
NOREF#2724  -  []  325.3 202 0 top
NOREF#2725  -  []  260.53 264.49 0 top
NOREF#2726  -  []  516.65 219.26 90 top
NOREF#2727  -  []  457.07 82.22 90 top
NOREF#2728  -  []  366.13 245.02 0 top
NOREF#2729  -  []  459.51 268.08 90 top
NOREF#2730  -  []  286.8 187.3 90 top
NOREF#2731  -  []  332.4 67.46 0 top
NOREF#2732  -  []  225.47 261.59 0 top
NOREF#2733  -  []  231.22 84.5 90 top
NOREF#2734  -  []  408.54 251.43 0 top
NOREF#2735  -  []  340.3 273 0 top
NOREF#2736  -  []  340.87 276.46 90 top
NOREF#2737  -  []  292.72 265.56 0 top
NOREF#2738  -  []  325.7 246.14 90 top
NOREF#2739  -  []  482.56 276.99 0 top
NOREF#2740  -  []  505.42 259.74 0 top
NOREF#2741  -  []  372.38 228.89 0 top
NOREF#2742  -  []  482.56 208.41 0 top
NOREF#2743  -  []  259.02 168.91 90 top
NOREF#2744  -  []  325.13 299.95 0 top
NOREF#2745  -  []  270.2 297.68 90 top
NOREF#2746  -  []  366.13 185.02 0 top
NOREF#2747  -  []  288.24 295.31 0 top
NOREF#2748  -  []  502.07 236.53 90 top
NOREF#2749  -  []  366.62 210 0 top
NOREF#2750  -  []  520.17 296.69 90 top
NOREF#2751  -  []  170.58 167.55 0 top
NOREF#2752  -  []  258.58 286.63 90 top
NOREF#2753  -  []  329.77 192.68 0 top
NOREF#2754  -  []  412.01 298.81 0 top
NOREF#2755  -  []  281.8 297.54 0 top
NOREF#2756  -  []  210.19 260.19 0 top
NOREF#2757  -  []  313.3 230 0 top
NOREF#2758  -  []  306.14 183.1 0 top
NOREF#2759  -  []  408.09 255.99 0 top
NOREF#2760  -  []  294.57 278.11 90 top
NOREF#2761  -  []  226.24 175.97 0 top
NOREF#2762  -  []  398.31 83.12 90 top
NOREF#2763  -  []  372.33 205.91 0 top
NOREF#2764  -  []  403.35 176.74 0 top
NOREF#2765  -  []  272.8 23.5 90 top
NOREF#2766  -  []  372.19 192 90 top
NOREF#2767  -  []  341.41 170.34 90 top
NOREF#2768  -  []  351.52 121.95 0 top
NOREF#2769  -  []  405.3 262 0 top
NOREF#2770  -  []  442.87 291.85 0 top
NOREF#2771  -  []  210.19 183.21 0 top
NOREF#2772  -  []  182.03 236.93 90 top
NOREF#2773  -  []  279.47 259.92 0 top
NOREF#2774  -  []  391.3 222 0 top
NOREF#2775  -  []  492.04 83.32 0 top
NOREF#2776  -  []  381.86 169.03 0 top
NOREF#2777  -  []  400.21 173.54 90 top
NOREF#2778  -  []  256.93 205.43 90 top
NOREF#2779  -  []  364.25 177.55 0 top
NOREF#2780  -  []  283.63 266.35 0 top
NOREF#2781  -  []  348.3 235 0 top
NOREF#2782  -  []  500.02 282.2 90 top
NOREF#2783  -  []  294.03 294.52 90 top
NOREF#2784  -  []  382.13 75.08 0 top
NOREF#2785  -  []  291.8 201.5 90 top
NOREF#2786  -  []  453.25 177.47 0 top
NOREF#2787  -  []  240.95 223.31 90 top
NOREF#2788  -  []  296.44 264.79 0 top
NOREF#2789  -  []  408.51 256.36 0 top
NOREF#2790  -  []  413.3 257.5 90 top
NOREF#2791  -  []  500.02 251.1 0 top
NOREF#2792  -  []  192.73 223.81 0 top
NOREF#2793  -  []  228.88 89.06 90 top
NOREF#2794  -  []  401.57 209.12 90 top
NOREF#2795  -  []  193.38 253.19 0 top
NOREF#2796  -  []  439.67 298.86 0 top
NOREF#2797  -  []  288.95 196.35 0 top
NOREF#2798  -  []  334.22 200.52 0 top
NOREF#2799  -  []  344.01 166.16 90 top
NOREF#2800  -  []  52.77 68.06 0 top
NOREF#2801  -  []  336.44 204.79 0 top
NOREF#2802  -  []  204.81 210.26 0 top
NOREF#2803  -  []  349.57 132.51 90 top
NOREF#2804  -  []  279.35 228.96 0 top
NOREF#2805  -  []  408.89 251.43 0 top
NOREF#2806  -  []  406.23 187.42 0 top
NOREF#2807  -  []  407.36 200.49 90 top
NOREF#2808  -  []  202.61 227.3 0 top
NOREF#2809  -  []  369.7 269.37 90 top
NOREF#2810  -  []  461.2 357.13 90 top
NOREF#2811  -  []  367.59 196.03 0 top
NOREF#2812  -  []  22.13 377.58 0 top
NOREF#2813  -  []  327.68 200.19 0 top
NOREF#2814  -  []  450.39 297.09 90 top
NOREF#2815  -  []  188.31 191.57 90 top
NOREF#2816  -  []  374.42 267.08 90 top
NOREF#2817  -  []  408.41 260.19 0 top
NOREF#2818  -  []  374.3 208.85 90 top
NOREF#2819  -  []  187.11 292.92 0 top
NOREF#2820  -  []  404.8 196.37 0 top
NOREF#2821  -  []  351.54 243.1 0 top
NOREF#2822  -  []  286.9 196.05 90 top
NOREF#2823  -  []  258.61 305.54 0 top
NOREF#2824  -  []  366.76 137.19 0 top
NOREF#2825  -  []  404.8 245.52 0 top
NOREF#2826  -  []  426.14 239.9 90 top
NOREF#2827  -  []  415.13 99.62 90 top
NOREF#2828  -  []  366.38 293.68 90 top
NOREF#2829  -  []  482.56 251.1 0 top
NOREF#2830  -  []  451.65 206.48 0 top
NOREF#2831  -  []  324.8 255.09 90 top
NOREF#2832  -  []  247.68 252.34 0 top
NOREF#2833  -  []  23.09 385.73 90 top
NOREF#2834  -  []  409.7 269.37 90 top
NOREF#2835  -  []  261.58 296.8 90 top
NOREF#2836  -  []  408.46 256.44 0 top
NOREF#2837  -  []  414.43 265.59 90 top
NOREF#2838  -  []  224.59 235.89 0 top
NOREF#2839  -  []  331.14 185.99 90 top
NOREF#2840  -  []  321.62 294.83 90 top
NOREF#2841  -  []  211.84 175.97 0 top
NOREF#2842  -  []  237.43 197.48 0 top
NOREF#2843  -  []  348.37 117.11 90 top
NOREF#2844  -  []  371.8 201.5 90 top
NOREF#2845  -  []  465.73 239.5 90 top
NOREF#2846  -  []  371.55 249.53 90 top
NOREF#2847  -  []  188.98 184.61 0 top
NOREF#2848  -  []  360.3 233 0 top
NOREF#2849  -  []  370.62 193.99 90 top
NOREF#2850  -  []  333.13 132.35 90 top
NOREF#2851  -  []  294.73 172.88 0 top
NOREF#2852  -  []  364.53 265.39 90 top
NOREF#2853  -  []  394.28 208.98 90 top
NOREF#2854  -  []  476.08 97.07 90 top
NOREF#2855  -  []  389.3 223 0 top
NOREF#2856  -  []  406.99 247.5 90 top
NOREF#2857  -  []  249.33 246.73 0 top
NOREF#2858  -  []  179.95 188.21 0 top
NOREF#2859  -  []  249.33 281.02 0 top
NOREF#2860  -  []  271.3 188 90 top
NOREF#2861  -  []  324.1 99.62 90 top
NOREF#2862  -  []  284.8 186.46 90 top
NOREF#2863  -  []  347.77 153.19 0 top
NOREF#2864  -  []  217.72 374.69 90 top
NOREF#2865  -  []  182.03 240.12 90 top
NOREF#2866  -  []  334.43 203.38 90 top
NOREF#2867  -  []  210.94 360.96 0 top
NOREF#2868  -  []  211.48 98.95 0 top
NOREF#2869  -  []  359.47 203.4 0 top
NOREF#2870  -  []  477.16 216.81 0 top
NOREF#2871  -  []  232.52 286.08 90 top
NOREF#2872  -  []  319.69 296.22 0 top
NOREF#2873  -  []  355.41 77.1 0 top
NOREF#2874  -  []  485.88 177.92 90 top
NOREF#2875  -  []  359.47 199.92 0 top
NOREF#2876  -  []  329.11 191.32 90 top
NOREF#2877  -  []  326.33 247.99 90 top
NOREF#2878  -  []  340.81 206.84 90 top
NOREF#2879  -  []  182.03 259.79 90 top
NOREF#2880  -  []  334.43 261.87 90 top
NOREF#2881  -  []  287.28 259.55 90 top
NOREF#2882  -  []  414.43 205.59 90 top
NOREF#2883  -  []  465.96 198.42 0 top
NOREF#2884  -  []  286.99 247.3 90 top
NOREF#2885  -  []  276.16 262.17 90 top
NOREF#2886  -  []  404.8 195.09 90 top
NOREF#2887  -  []  405.13 195.99 0 top
NOREF#2888  -  []  370.3 266.6 90 top
NOREF#2889  -  []  405.1 254.08 0 top
NOREF#2890  -  []  396.1 286.51 0 top
NOREF#2891  -  []  500.02 225.45 0 top
NOREF#2892  -  []  369.3 191.52 90 top
NOREF#2893  -  []  365.7 188.02 0 top
NOREF#2894  -  []  410.18 299.74 90 top
NOREF#2895  -  []  364.8 186.46 0 top
NOREF#2896  -  []  332.17 249.51 90 top
NOREF#2897  -  []  317.89 122.11 0 top
NOREF#2898  -  []  408.5 270.01 0 top
NOREF#2899  -  []  246.78 192.31 0 top
NOREF#2900  -  []  401.55 288.95 0 top
NOREF#2901  -  []  446.56 97.42 90 top
NOREF#2902  -  []  324.8 208.5 0 top
NOREF#2903  -  []  221.09 208.86 90 top
NOREF#2904  -  []  488.59 298.09 90 top
NOREF#2905  -  []  511.37 290.22 0 top
NOREF#2906  -  []  359.7 298.81 0 top
NOREF#2907  -  []  272.28 261.88 0 top
NOREF#2908  -  []  465.96 191.16 0 top
NOREF#2909  -  []  414.3 200.8 90 top
NOREF#2910  -  []  339.73 98.95 0 top
NOREF#2911  -  []  413.22 267.72 0 top
NOREF#2912  -  []  310.51 360.96 0 top
NOREF#2913  -  []  289.66 195.8 90 top
NOREF#2914  -  []  313.78 83.52 90 top
NOREF#2915  -  []  508.3 173.03 90 top
NOREF#2916  -  []  374.5 189.29 90 top
NOREF#2917  -  []  326.08 260.19 0 top
NOREF#2918  -  []  482.56 232.71 0 top
NOREF#2919  -  []  364.1 259 0 top
NOREF#2920  -  []  366.99 247.3 90 top
NOREF#2921  -  []  413.22 204.81 0 top
NOREF#2922  -  []  370.76 255.38 0 top
NOREF#2923  -  []  372.33 262.19 0 top
NOREF#2924  -  []  293.93 273.57 0 top
NOREF#2925  -  []  287.13 82.22 90 top
NOREF#2926  -  []  258.58 245.33 90 top
NOREF#2927  -  []  189.51 224.34 90 top
NOREF#2928  -  []  451.65 172.19 0 top
NOREF#2929  -  []  416.84 169.02 0 top
NOREF#2930  -  []  336.9 373.84 0 top
NOREF#2931  -  []  317.89 117.11 90 top
NOREF#2932  -  []  413.03 213.89 0 top
NOREF#2933  -  []  349.57 147.75 90 top
NOREF#2934  -  []  315.45 103.62 0 top
NOREF#2935  -  []  346.68 208.98 0 top
NOREF#2936  -  []  373.23 204.02 0 top
NOREF#2937  -  []  442.87 264.57 0 top
NOREF#2938  -  []  285.97 253.75 0 top
NOREF#2939  -  []  388.54 166.49 90 top
NOREF#2940  -  []  516.65 293.89 0 top
NOREF#2941  -  []  249.33 178.15 0 top
NOREF#2942  -  []  368.24 295.31 90 top
NOREF#2943  -  []  406.25 195.33 0 top
NOREF#2944  -  []  480.8 424.5 90 top
NOREF#2945  -  []  310.18 71.55 0 top
NOREF#2946  -  []  364.75 218.11 90 top
NOREF#2947  -  []  242.47 258.54 90 top
NOREF#2948  -  []  436.7 83.12 90 top
NOREF#2949  -  []  330.97 245.28 0 top
NOREF#2950  -  []  23.09 365.41 90 top
NOREF#2951  -  []  491.79 198.42 0 top
NOREF#2952  -  []  223.27 295.88 0 top
NOREF#2953  -  []  318.05 150.74 90 top
NOREF#2954  -  []  368.3 265 0 top
NOREF#2955  -  []  210.29 86.94 90 top
NOREF#2956  -  []  332.38 198.4 0 top
NOREF#2957  -  []  500.02 216.81 0 top
NOREF#2958  -  []  230.87 295.88 90 top
NOREF#2959  -  []  465.73 242.7 0 top
NOREF#2960  -  []  373.47 252.26 0 top
NOREF#2961  -  []  258.58 176.75 90 top
NOREF#2962  -  []  366.76 152.43 0 top
NOREF#2963  -  []  487.51 88.56 90 top
NOREF#2964  -  []  294.22 196.16 90 top
NOREF#2965  -  []  407.93 244.02 90 top
NOREF#2966  -  []  315 361.76 0 top
NOREF#2967  -  []  364.8 246.46 90 top
NOREF#2968  -  []  405.13 255.99 0 top
NOREF#2969  -  []  232.25 373.84 0 top
NOREF#2970  -  []  417.34 264.47 90 top
NOREF#2971  -  []  328.54 251.43 0 top
NOREF#2972  -  []  412.17 249.51 90 top
NOREF#2973  -  []  204.81 253.19 0 top
NOREF#2974  -  []  410.3 266.6 90 top
NOREF#2975  -  []  488.59 285.39 0 top
NOREF#2976  -  []  319.09 117.27 90 top
NOREF#2977  -  []  373.02 257.65 0 top
NOREF#2978  -  []  326.25 255.33 0 top
NOREF#2979  -  []  336.44 203.42 0 top
NOREF#2980  -  []  287 247.55 90 top
NOREF#2981  -  []  451.12 181.62 0 top
NOREF#2982  -  []  324.1 199 0 top
NOREF#2983  -  []  320.9 102.82 0 top
NOREF#2984  -  []  334.57 220.31 90 top
NOREF#2985  -  []  369.87 256.73 0 top
NOREF#2986  -  []  414.22 257.01 90 top
NOREF#2987  -  []  332.17 244.64 90 top
NOREF#2988  -  []  514.57 216.24 90 top
NOREF#2989  -  []  261.69 226.21 90 top
NOREF#2990  -  []  240.95 189.66 0 top
NOREF#2991  -  []  449.82 243.4 0 top
NOREF#2992  -  []  439.67 295.66 90 top
NOREF#2993  -  []  299.66 90.74 0 top
NOREF#2994  -  []  262.56 230.02 0 top
NOREF#2995  -  []  364.8 188.34 0 top
NOREF#2996  -  []  312.28 76.38 0 top
NOREF#2997  -  []  379.4 293.92 0 top
NOREF#2998  -  []  383.08 167.76 0 top
NOREF#2999  -  []  514.57 296.25 90 top
NOREF#3000  -  []  405.7 188.02 0 top
NOREF#3001  -  []  366.9 196.05 90 top
NOREF#3002  -  []  321.57 200.33 90 top
NOREF#3003  -  []  366.62 270 0 top
NOREF#3004  -  []  271.3 222 0 top
NOREF#3005  -  []  269.18 196.09 90 top
NOREF#3006  -  []  516.65 179.59 0 top
NOREF#3007  -  []  294.58 295.32 0 top
NOREF#3008  -  []  410.07 252.35 0 top
NOREF#3009  -  []  408.17 333.65 0 top
NOREF#3010  -  []  471.13 174.12 0 top
NOREF#3011  -  []  303.55 360.96 0 top
NOREF#3012  -  []  459.82 211.66 90 top
NOREF#3013  -  []  272.8 424.5 90 top
NOREF#3014  -  []  328.09 195.99 0 top
NOREF#3015  -  []  279.15 208.8 0 top
NOREF#3016  -  []  198.23 270.18 90 top
NOREF#3017  -  []  333.13 152.59 0 top
NOREF#3018  -  []  208.01 278.84 90 top
NOREF#3019  -  []  272.07 82 0 top
NOREF#3020  -  []  451.91 199.82 0 top
NOREF#3021  -  []  288.56 254.22 0 top
NOREF#3022  -  []  213.03 301.57 0 top
NOREF#3023  -  []  216.24 287.48 0 top
NOREF#3024  -  []  320.97 89.89 0 top
NOREF#3025  -  []  328.1 259.55 90 top
NOREF#3026  -  []  334.67 191.62 90 top
NOREF#3027  -  []  275.07 81.48 90 top
NOREF#3028  -  []  324.5 186.78 0 top
NOREF#3029  -  []  505.92 199.59 0 top
NOREF#3030  -  []  349.18 258.29 90 top
NOREF#3031  -  []  410.32 255.4 0 top
NOREF#3032  -  []  290.9 202.85 90 top
NOREF#3033  -  []  363.77 120.91 0 top
NOREF#3034  -  []  406.55 169.14 90 top
NOREF#3035  -  []  348.53 151.39 0 top
NOREF#3036  -  []  407.38 258.01 0 top
NOREF#3037  -  []  411.37 285.71 0 top
NOREF#3038  -  []  52.77 405.06 0 top
NOREF#3039  -  []  198.76 294.48 0 top
NOREF#3040  -  []  406.33 247.99 90 top
NOREF#3041  -  []  476.47 373.84 90 top
NOREF#3042  -  []  268.3 185 90 top
NOREF#3043  -  []  328.54 191.43 0 top
NOREF#3044  -  []  294.3 200.8 90 top
NOREF#3045  -  []  462.76 195.22 90 top
NOREF#3046  -  []  327.59 256.03 0 top
NOREF#3047  -  []  219.44 278.84 90 top
NOREF#3048  -  []  320.37 200.97 0 top
NOREF#3049  -  []  368.67 255.4 90 top
NOREF#3050  -  []  339.2 167.5 90 top
NOREF#3051  -  []  495.27 238.48 90 top
NOREF#3052  -  []  50.8 465 0 top
NOREF#3053  -  []  271.3 222 0 top
NOREF#3054  -  []  282.3 256.5 0 top
NOREF#3055  -  []  320.37 263.08 0 top
NOREF#3056  -  []  356.1 226.51 0 top
NOREF#3057  -  []  372.7 190.29 0 top
NOREF#3058  -  []  400.37 259.6 0 top
NOREF#3059  -  []  363.63 205.5 0 top
NOREF#3060  -  []  325.92 226.51 0 top
NOREF#3061  -  []  187.33 270.18 0 top
NOREF#3062  -  []  450.39 194.22 90 top
NOREF#3063  -  []  187.33 167.31 0 top
NOREF#3064  -  []  453.76 273.79 0 top
NOREF#3065  -  []  232.52 251.79 90 top
NOREF#3066  -  []  319.09 147.75 90 top
NOREF#3067  -  []  442.87 250.55 0 top
NOREF#3068  -  []  363.98 198.4 90 top
NOREF#3069  -  []  406.08 200.19 0 top
NOREF#3070  -  []  202.8 45.5 0 top
NOREF#3071  -  []  336.28 152.43 0 top
NOREF#3072  -  []  390.3 293.92 90 top
NOREF#3073  -  []  413.92 264.92 90 top
NOREF#3074  -  []  488.59 247.91 90 top
NOREF#3075  -  []  404.8 188.34 0 top
NOREF#3076  -  []  341.41 167.75 90 top
NOREF#3077  -  []  293.28 269.37 90 top
NOREF#3078  -  []  284.48 186.16 0 top
NOREF#3079  -  []  292.38 258.4 0 top
NOREF#3080  -  []  365.7 244.32 90 top
NOREF#3081  -  []  193.38 168.71 0 top
NOREF#3082  -  []  316.16 202.17 90 top
NOREF#3083  -  []  406.61 81.48 90 top
NOREF#3084  -  []  27.57 381.89 0 top
NOREF#3085  -  []  511.37 221.64 0 top
NOREF#3086  -  []  332.33 202.19 0 top
